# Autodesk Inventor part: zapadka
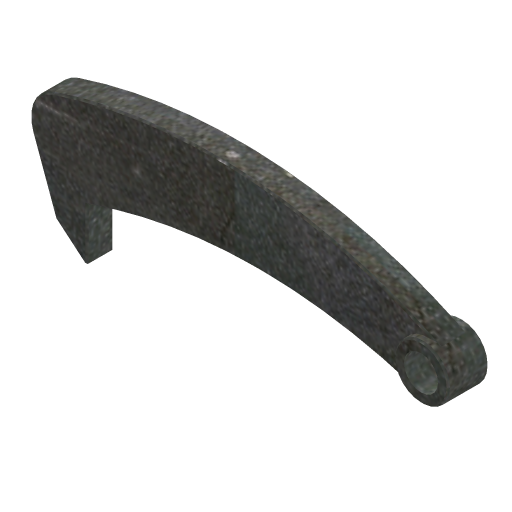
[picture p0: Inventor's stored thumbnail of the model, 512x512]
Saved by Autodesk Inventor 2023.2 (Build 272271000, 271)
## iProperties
Created: 2022-12
Part Number: zapadka
Material: Stal
Document SubType Name: Modeling
Designer: TEST
Density: 7.85 g/cm^3
Appearance: Płyta
Mass: 14.5571 g
Surface Area: 61.5674 cm^2
Volume: 14.5571 cm^3
Author: TEST
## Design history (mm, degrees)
sketch "Szkic1"
  geometry: L1 (-100, -23.301)-(-100, -8.373); L2 (-100.821, -23.684)-(-109.367, -16.513); L3 (-109.367, -16.513)-(-116.208, 2.281); C1 r 5 at (0, 0); A1 r 8 centre (0, 0) between (-2.538, -7.587) and (3.549, 7.17); A2 r 150 centre (-50.124, -149.838) between (-2.538, -7.587) and (-100, -8.373); A3 r 150 centre (-62.99, -127.264) between (3.549, 7.17) and (-109.941, 15.199); A4 r 0.5 centre (-100.5, -23.301) between (-100.821, -23.684) and (-100, -23.301); A5 r 10 centre (-106.811, 5.701) between (-109.941, 15.199) and (-116.208, 2.281); 3 further points
  constraints: 11 point on circle, 6 centre point, 6 end point, 6 tangent, 3 point on line, 2 coincident, 1 equal radius, 1 vertical
  dimensions: "d0" = 10 diameter of C1; "d1" = 16 diameter of A1; "d2" = 16 distance of point (-100, -24.373) L1.end; "d3" = 100 distance from line of point (0, 0) L1; "d8" = 150 radius of A2; "d9" = 0.5 radius of A4; "d10" = 10 radius of A5; "d15" = 50 deg angle of L1 L2; "d16" = 150 deg angle of L2 L3; "d17" = 20 distance of L2.end L3.end
extrude "Wyciągnięcie proste1" new body sketch "Szkic1" stored distance "d11" = 8; taper "d12" = 0 deg
extrude "Wyciągnięcie proste2" join sketch "Szkic1" stored distance "d13" = 12; taper "d14" = 0 deg
chamfer "Faza1" distance "d18" = 0.5; stored, may be unused: second distance "d19" = 2, angle "d20" = 45 deg
node "Bryła1"
